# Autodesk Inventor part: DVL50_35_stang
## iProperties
Created: 2009-07
Part Number: DVL50_35_stang
Document SubType Name: Modeling
Designer: TB
Mass: 248.451 g
Surface Area: 295.876 cm^2
Volume: 248.451 cm^3
Density: 1 g/cm^3
Author: TB
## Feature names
1. Revolution1
2. Fillet1
3. Revolution2
